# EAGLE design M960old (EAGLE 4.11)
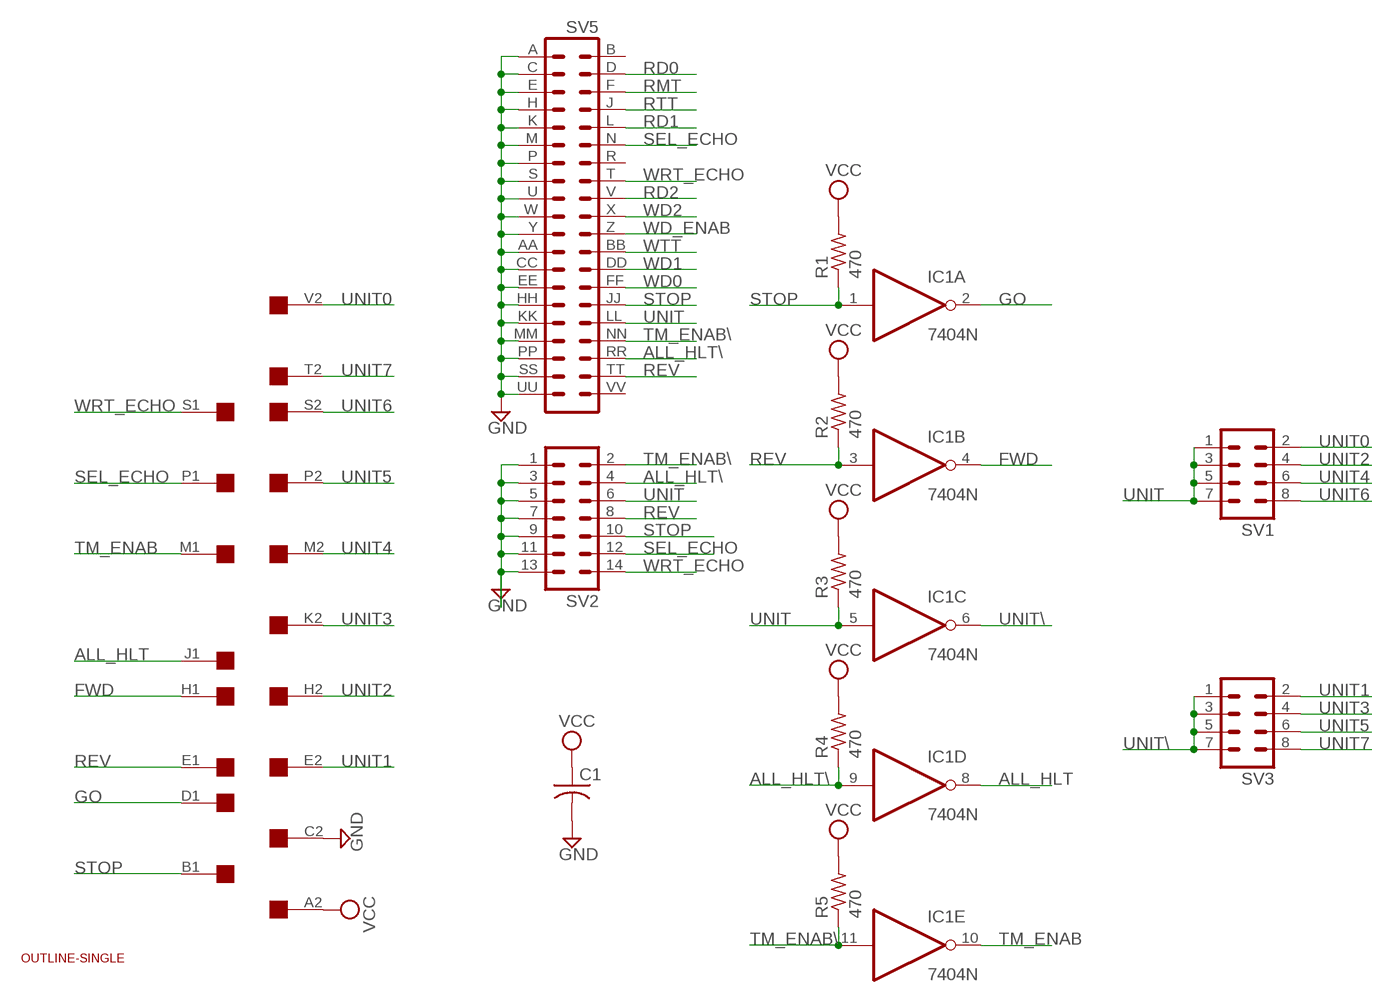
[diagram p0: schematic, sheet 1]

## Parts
C1  C-US050-025X075  [C050-025X075]
IC1  7404N  [DIL14]
R1  470  R-US_0207/10  [0207/10]
R2  470  R-US_0207/10  [0207/10]
R3  470  R-US_0207/10  [0207/10]
R4  470  R-US_0207/10  [0207/10]
R5  470  R-US_0207/10  [0207/10]
SV1  MA04-2  [MA04-2]
SV2  MA07-2  [MA07-2]
SV3  MA04-2  [MA04-2]
SV5  DEC40PIN  [DEC40PIN]
U$1  OUTLINE-SINGLE  [SINGLE]
U$2  SINGLE  [EDGE-CON2]

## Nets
ALL_HLT: IC1.8(D:O) U$2.J1
ALL_HLT\: IC1.9(D:I) R4.1 SV2.4 SV5.RR
FWD: IC1.4(B:O) U$2.H1
GND: C1.2 SV2.1 SV2.3 SV2.5 SV2.7 SV2.9 SV2.11 SV2.13 SV5.A SV5.AA SV5.C SV5.CC SV5.E SV5.EE SV5.H SV5.HH SV5.K SV5.KK SV5.M SV5.MM SV5.P SV5.PP SV5.S SV5.SS SV5.U SV5.UU SV5.W SV5.Y U$2.C2
GO: IC1.2(A:O) U$2.D1
RD0: SV5.D
RD1: SV5.L
RD2: SV5.V
REV: IC1.3(B:I) R2.1 SV2.8 SV5.TT U$2.E1
RMT: SV5.F
RTT: SV5.J
SEL_ECHO: SV2.12 SV5.N U$2.P1
STOP: IC1.1(A:I) R1.1 SV2.10 SV5.JJ U$2.B1
TM_ENAB: IC1.10(E:O) U$2.M1
TM_ENAB\: IC1.11(E:I) R5.1 SV2.2 SV5.NN
UNIT: IC1.5(C:I) R3.1 SV1.1 SV1.3 SV1.5 SV1.7 SV2.6 SV5.LL
UNIT0: SV1.2 U$2.V2
UNIT1: SV3.2 U$2.E2
UNIT2: SV1.4 U$2.H2
UNIT3: SV3.4 U$2.K2
UNIT4: SV1.6 U$2.M2
UNIT5: SV3.6 U$2.P2
UNIT6: SV1.8 U$2.S2
UNIT7: SV3.8 U$2.T2
UNIT\: IC1.6(C:O) SV3.1 SV3.3 SV3.5 SV3.7
VCC: C1.1 R1.2 R2.2 R3.2 R4.2 R5.2 U$2.A2
WD0: SV5.FF
WD1: SV5.DD
WD2: SV5.X
WD_ENAB: SV5.Z
WRT_ECHO: SV2.14 SV5.T U$2.S1
WTT: SV5.BB
Unconnected: IC1.12(F:O) IC1.13(F:I) SV5.B SV5.R SV5.VV U$2.A1 U$2.B2 U$2.C1 U$2.D2 U$2.F1 U$2.F2 U$2.J2 U$2.K1 U$2.L1 U$2.L2 U$2.N1 U$2.N2 U$2.R1 U$2.R2 U$2.T1 U$2.U1 U$2.U2 U$2.V1

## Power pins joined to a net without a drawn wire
GND: IC1.7(P:GND)
VCC: IC1.14(P:VCC)

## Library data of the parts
C1 = rcl:C-US: CAPACITOR, American symbol
IC1 = 74xx-us:74*04: Hex INVERTER
R1-R5 = rcl:R-US_: RESISTOR, American symbol
SV1 SV3 = con-lstb:MA04-2: PIN HEADER
SV2 = con-lstb:MA07-2: PIN HEADER
SV5 = dec-con:DEC40PIN: PIN HEADER
U$1 = dec-con:OUTLINE-*: Board outlines for DEC boards.
U$2 = dec-con:SINGLE: Double-Height DEC board

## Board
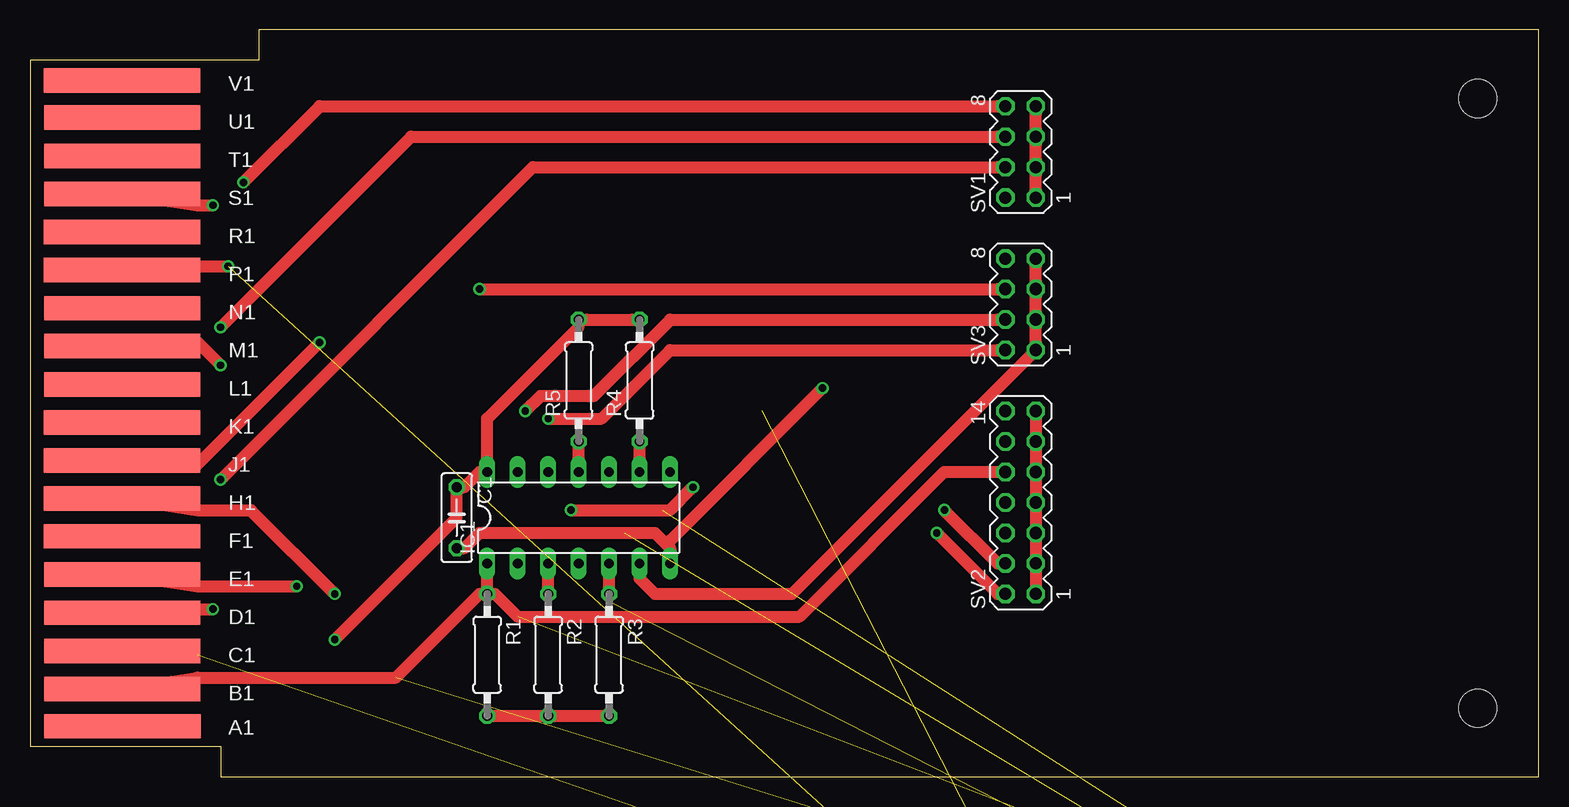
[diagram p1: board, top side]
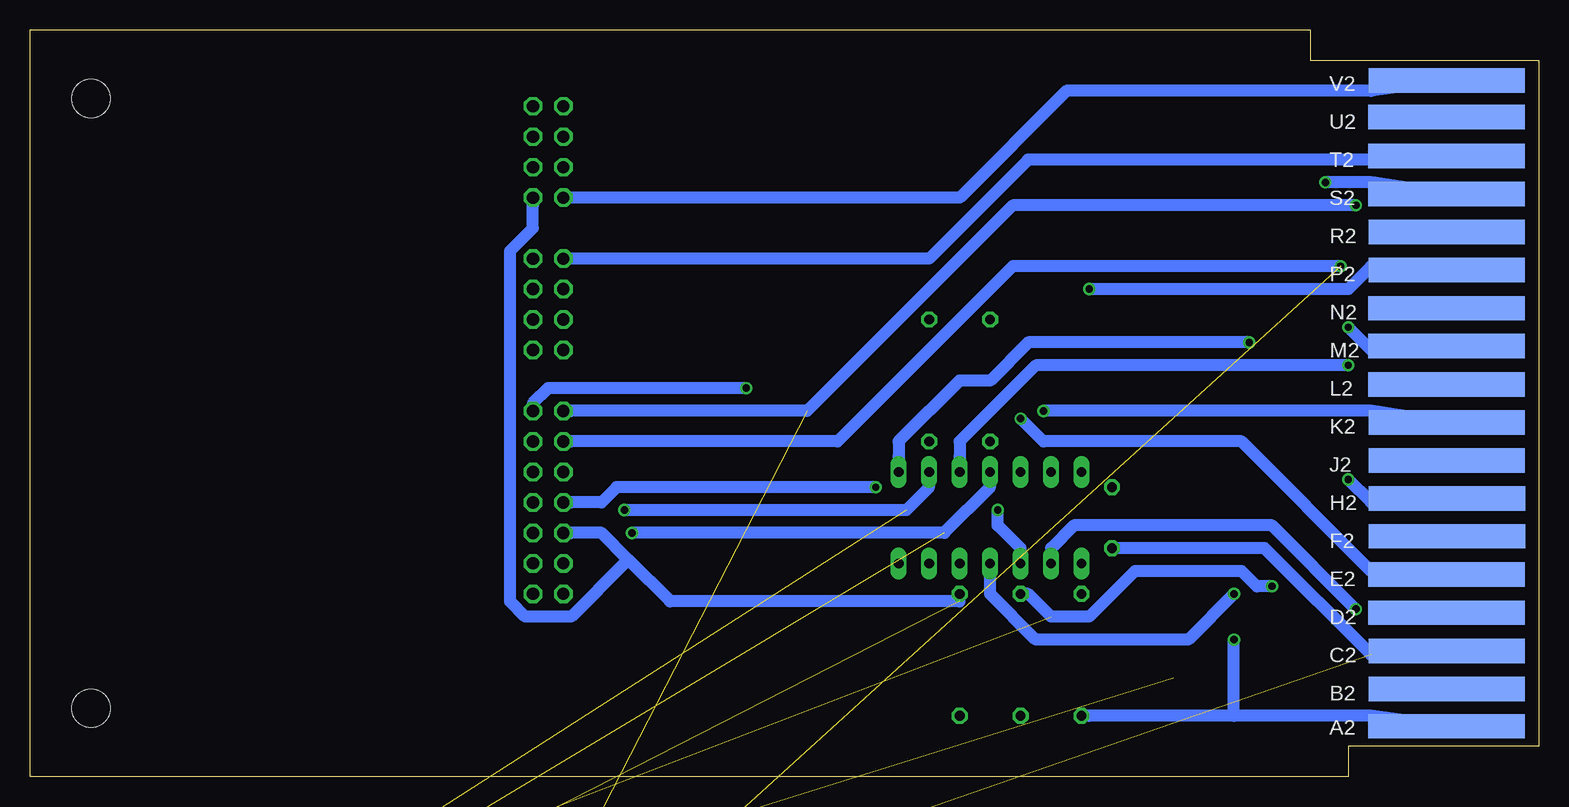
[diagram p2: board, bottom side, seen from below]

Size 125.73 x 62.23 mm. Coordinates in mm from the lower left corner, seen from the top.
Copper layers (1*16): Top 0.035mm / dielectric 1.5mm / Bottom 0.035mm
Design rules "15mils": minimum track width 40mil, minimum drill 24mil, track to track 20mil, track to pad 10mil, pad to pad 10mil, via to via 10mil, smd to smd 10mil, copper to edge 25mil, drill to drill 10mil, minimum pad ring 10mil, minimum via ring 8mil, stop-mask expansion 0mil, vias tented up to drill 0mil, thermal gap 10mil

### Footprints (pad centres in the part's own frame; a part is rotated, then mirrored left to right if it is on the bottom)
C050-025X075 = drill 0.813 octagon: 1 -2.54,0; 2 2.54,0
DIL14 = drill 0.813 long: 1 -7.62,-3.81; 2 -5.08,-3.81; 3 -2.54,-3.81; 4 0,-3.81; 5 2.54,-3.81; 6 5.08,-3.81; 7 7.62,-3.81; 8 7.62,3.81; 9 5.08,3.81; 10 2.54,3.81; 11 0,3.81; 12 -2.54,3.81; 13 -5.08,3.81; 14 -7.62,3.81
0207/10 = drill 0.813 octagon: 1 -5.08,0; 2 5.08,0
MA04-2 = drill 1.016 octagon: 1 -3.81,-1.27; 2 -3.81,1.27; 3 -1.27,-1.27; 4 -1.27,1.27; 5 1.27,-1.27; 6 1.27,1.27; 7 3.81,-1.27; 8 3.81,1.27
MA07-2 = drill 1.016 octagon: 1 -7.62,-1.27; 2 -7.62,1.27; 3 -5.08,-1.27; 4 -5.08,1.27; 5 -2.54,-1.27; 6 -2.54,1.27; 7 0,-1.27; 8 0,1.27; 9 2.54,-1.27; 10 2.54,1.27; 11 5.08,-1.27; 12 5.08,1.27; 13 7.62,-1.27; 14 7.62,1.27
DEC40PIN = drill 1.016 octagon: A -24.13,1.27; AA 3.81,1.27; B -24.13,-1.27; BB 3.81,-1.27; C -21.59,1.27; CC 6.35,1.27; D -21.59,-1.27; DD 6.35,-1.27; E -19.05,1.27; EE 8.89,1.27; F -19.05,-1.27; FF 8.89,-1.27; H -16.51,1.27; HH 11.43,1.27; J -16.51,-1.27; JJ 11.43,-1.27; K -13.97,1.27; KK 13.97,1.27; L -13.97,-1.27; LL 13.97,-1.27; M -11.43,1.27; MM 16.51,1.27; N -11.43,-1.27; NN 16.51,-1.27; P -8.89,1.27; PP 19.05,1.27; R -8.89,-1.27; RR 19.05,-1.27; S -6.35,1.27; SS 21.59,1.27; T -6.35,-1.27; TT 21.59,-1.27; U -3.81,1.27; UU 24.13,1.27; V -3.81,-1.27; VV 24.13,-1.27; W -1.27,1.27; X -1.27,-1.27; Y 1.27,1.27; Z 1.27,-1.27
SINGLE = hole 3.175: 120.65,56.515; 120.65,5.715
EDGE-CON2 = smd 13.017 x 2.032: A1 7.709,4.207; B1 7.684,7.312; C1 7.684,10.474; D1 7.684,13.665; E1 7.693,16.84; F1 7.668,20.041; H1 7.668,23.19; J1 7.668,26.34; K1 7.668,29.515; L1 7.693,32.69; M1 7.693,35.89; N1 7.693,39.04; P1 7.668,42.24; R1 7.668,45.39; S1 7.693,48.565; T1 7.693,51.74; U1 7.693,54.94; V1 7.668,58.026 | smd 13.017 x 2.032 bottom: A2 7.69,4.207; B2 7.668,7.328; C2 7.668,10.49; D2 7.693,13.665; E2 7.693,16.84; F2 7.642,20.041; H2 7.642,23.19; J2 7.668,26.34; K2 7.668,29.515; L2 7.693,32.69; M2 7.693,35.89; N2 7.693,39.04; P2 7.668,42.24; R2 7.668,45.39; S2 7.693,48.565; T2 7.693,51.74; U2 7.693,54.966; V2 7.668,58.026

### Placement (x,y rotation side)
C1  35.56,21.59 270 top
IC1  45.72,21.59 0 top
R1  38.1,10.16 270 top
R2  43.18,10.16 270 top
R3  48.26,10.16 270 top
R4  50.8,33.02 90 top
R5  45.72,33.02 90 top
SV1  82.55,52.07 90 top
SV2  82.55,22.86 90 top
SV3  82.55,39.37 90 top
SV5  not placed on the board
U$1  0,0 0 top
U$2  0,0 0 top

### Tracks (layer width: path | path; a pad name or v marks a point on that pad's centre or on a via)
ALL_HLT  (via drill 0.61)
  Top 1.016: v24.13,36.2 13.97,26.04 U$2.J1
  Bottom 1.016: v24.13,36.2 42.55,36.2 45.72,33.02 48.26,33.02 53.34,27.94 53.34,26.67 IC1.8
ALL_HLT\  (via drill 0.61)  (1 unrouted)
  Top 1.016: IC1.9 50.8,26.67 50.8,27.3 R4.1 | v76.2,22.23 80.65,17.78 SV2.4
  Bottom 1.016: v76.2,22.23 52.71,22.23 50.8,24.13 IC1.9
FWD  (via drill 0.61)
  Top 1.016: v25.4,15.24 18.42,22.23 13.97,22.23 U$2.H1
  Bottom 1.016: v25.4,15.24 29.21,11.43 41.91,11.43 45.72,15.24 45.72,16.51 IC1.4
GND  (via drill 0.61)  (20 unrouted)
  Top 1.016: SV2.1 83.82,15.88 83.82,17.14 SV2.3 83.82,18.41 83.82,19.68 SV2.5 83.82,20.95 83.82,22.23 SV2.7 83.82,23.5 83.82,24.77 SV2.9 83.82,26.04 83.82,27.3 SV2.11 83.82,28.57 83.82,29.84 SV2.13 | 53.02,19.37 52.07,20.32 37.47,20.32 36.2,19.05 C1.2 | 53.02,19.37 53.34,19.05 IC1.7 | v66.04,32.38 53.34,19.68 53.02,19.37
  Bottom 1.016: C1.2 34.93,19.05 22.86,19.05 13.97,10.16 U$2.C2 | v66.04,32.38 82.55,32.38 83.82,31.11 SV2.13
GO  (via drill 0.61)
  Top 1.016: v15.24,13.97 13.97,13.97 U$2.D1
  Bottom 1.016: v15.24,13.97 22.23,20.95 38.74,20.95 40.64,19.05 IC1.2
REV  (via drill 0.61)  (1 unrouted)
  Top 1.016: R2.1 43.18,15.88 43.18,16.51 IC1.3 | v55.25,24.13 53.34,22.23 v45.09,22.23 | v22.23,15.88 13.97,15.88 U$2.E1
  Bottom 1.016: v55.25,24.13 76.84,24.13 78.11,22.86 80.65,22.86 SV2.8 | v45.09,22.23 45.09,20.95 43.18,19.05 IC1.3 | v22.23,15.88 23.5,15.88 24.77,17.14 33.66,17.14 37.47,13.34 40.64,13.34 42.55,15.24 R2.1
SEL_ECHO  (via drill 0.61)  (1 unrouted)
  Top 1.016: v16.51,42.55 13.97,42.55 U$2.P1
  Bottom 1.016: v16.51,42.55 43.82,42.55 58.42,27.94 80.65,27.94 SV2.12
STOP  (1 unrouted)
  Top 1.016: R1.1 38.1,15.88 38.1,16.51 IC1.1 | SV2.10 80.65,25.4 76.2,25.4 64.14,13.34 40.64,13.34 38.74,15.24 R1.1 | U$2.B1 13.97,8.26 30.48,8.26 37.47,15.24 R1.1
TM_ENAB  (via drill 0.61)
  Top 1.016: v15.88,34.29 13.97,36.2 U$2.M1
  Bottom 1.016: v15.88,34.29 41.91,34.29 48.26,27.94 48.26,26.67 IC1.10
TM_ENAB\  (via drill 0.61)  (1 unrouted)
  Top 1.016: IC1.11 45.72,26.67 45.72,27.3 R5.1 | v75.57,20.32 80.65,15.24 SV2.2
  Bottom 1.016: v75.57,20.32 49.53,20.32 45.72,24.13 IC1.11
UNIT  (1 unrouted)
  Top 1.016: SV1.1 83.82,48.9 83.82,50.16 SV1.3 83.82,51.44 83.82,52.7 SV1.5 83.82,53.98 83.82,55.24 SV1.7 | R3.1 48.26,15.88 48.26,16.51 IC1.5
  Bottom 1.016: 75.88,18.1 72.39,14.61 48.26,14.61 R3.1 | 75.88,18.1 78.11,20.32 80.65,20.32 SV2.6 | SV1.1 83.82,47.62 83.82,45.72 85.73,43.81 85.73,14.61 84.46,13.34 80.65,13.34 76.2,17.78 75.88,18.1
UNIT0
  Bottom 1.016: SV1.2 80.65,48.26 48.26,48.26 39.37,57.15 13.97,57.15 U$2.V2
UNIT1  (via drill 0.61)
  Top 1.016: v43.18,29.84 47.63,29.84 53.34,35.56 80.65,35.56 SV3.2
  Bottom 1.016: v43.18,29.84 41.28,27.94 24.77,27.94 13.97,17.14 U$2.E2
UNIT2  (via drill 0.61)
  Top 1.016: v15.88,24.77 41.91,50.8 80.65,50.8 SV1.4
  Bottom 1.016: v15.88,24.77 13.97,22.86 U$2.H2
UNIT3  (via drill 0.61)
  Top 1.016: v41.28,30.48 42.55,31.75 46.99,31.75 53.34,38.1 80.65,38.1 SV3.4
  Bottom 1.016: v41.28,30.48 13.97,30.48 U$2.K2
UNIT4  (via drill 0.61)
  Top 1.016: v15.88,37.47 31.75,53.34 80.65,53.34 SV1.6
  Bottom 1.016: v15.88,37.47 13.97,35.56 U$2.M2
UNIT5  (via drill 0.61)
  Top 1.016: v37.47,40.64 80.65,40.64 SV3.6
  Bottom 1.016: v37.47,40.64 15.88,40.64 13.97,42.55 U$2.P2
UNIT6  (via drill 0.61)
  Top 1.016: v17.78,49.53 24.13,55.88 80.65,55.88 SV1.8
  Bottom 1.016: v17.78,49.53 13.97,49.53 U$2.S2
UNIT7
  Bottom 1.016: SV3.8 80.65,43.18 50.8,43.18 42.55,51.44 13.97,51.44 U$2.T2
UNIT\
  Top 1.016: IC1.6 50.8,16.51 52.07,15.24 63.5,15.24 SV3.1 83.82,36.2 83.82,37.47 SV3.3 83.82,38.73 83.82,40.01 SV3.5 83.82,41.27 83.82,42.55 SV3.7
VCC  (via drill 0.61)
  Top 1.016: R4.2 50.17,38.1 46.36,38.1 R5.2 45.72,37.47 38.1,29.84 38.1,26.67 IC1.14 37.47,25.4 36.2,24.13 C1.1 35.56,23.5 35.56,21.59 v25.4,11.43 | R1.2 38.74,5.08 42.55,5.08 R2.2 43.82,5.08 47.63,5.08 R3.2
  Bottom 1.016: 25.4,5.08 13.97,5.08 U$2.A2 | 25.4,5.08 37.47,5.08 R1.2 | 25.4,5.08 v25.4,11.43
WRT_ECHO  (via drill 0.61)  (1 unrouted)
  Top 1.016: v15.24,47.62 13.97,47.62 U$2.S1
  Bottom 1.016: v15.24,47.62 43.82,47.62 60.96,30.48 80.65,30.48 SV2.14

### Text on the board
tValues: Unit7 | Unit5 | Unit3 | Unit1 | Unit6 | Unit4 | Unit2 | Unit0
